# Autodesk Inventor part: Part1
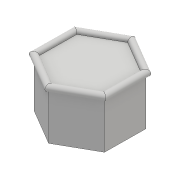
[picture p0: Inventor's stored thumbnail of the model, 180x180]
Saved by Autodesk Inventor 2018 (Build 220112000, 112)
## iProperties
Created: 2015-07
Part Number: Part1
Material: Generic
Document SubType Name: Modeling
Designer: Sandeep
Density: 1 g/cm^3
Appearance: Default
Author: Sandeep
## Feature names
1. Extrusion1
2. Sweep2
## Parameters: d0 = 8 mm, d1 = 0, d4 = 0, d5 = 0
